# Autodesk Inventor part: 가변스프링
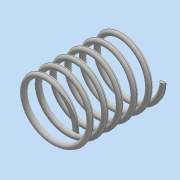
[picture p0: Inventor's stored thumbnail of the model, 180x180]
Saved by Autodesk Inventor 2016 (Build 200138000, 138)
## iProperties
Created: 2018-11
Part Number: 가변스프링
Material: 일반
Document SubType Name: Modeling
Designer: user
Density: 1 g/cm^3
Appearance: 기본값
Mass: 10.5248 g
Surface Area: 106.476 cm^2
Volume: 10.5248 cm^3
Author: user
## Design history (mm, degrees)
sketch "스케치1"
  geometry: L1 (0, 0)-(22.5, 0); L2 (22.5, 0)-(22.5, 67.25); L3 (22.5, 67.25)-(0, 67.25); L4 (0, 67.25)-(0, 0); C1 r 2 at (22.5, 0)
  constraints: 8 end point, 2 parallel, 1 centre point, 1 coincident, 1 horizontal, 1 perpendicular
  dimensions: "d0" = 67.25 distance between parallel lines of L1 L3 (derived); "d1" = 45 diameter of L2 L4; "d2" = 4 diameter of C1
feature "코일1" sketch "스케치1" pitch "d3" = 10; turns "d5" = 6; dims "d4" = 67.25 (= d0), "d6" = 0, angle "d7" = 90 deg, angle "d8" = 90 deg, "d9" = 0, "d10" = 0
sketch "스케치2"
  geometry: L1 (0, 30)-(67.25, 30); L2 (67.25, 30)-(67.25, -30); L3 (67.25, -30)-(0, -30); L4 (0, -30)-(0, 30); 2 further points
  constraints: 8 end point, 2 parallel, 1 coincident, 1 horizontal, 1 midpoint, 1 perpendicular
  dimensions: "d11" = 67.25 distance between parallel lines of L4 L2 (= d0); "d12" = 60 distance between parallel lines of L3 L1
extrude "돌출1" sketch "스케치2" stored distance "d13" = 100; taper "d14" = 0 deg
node "솔리드1"
